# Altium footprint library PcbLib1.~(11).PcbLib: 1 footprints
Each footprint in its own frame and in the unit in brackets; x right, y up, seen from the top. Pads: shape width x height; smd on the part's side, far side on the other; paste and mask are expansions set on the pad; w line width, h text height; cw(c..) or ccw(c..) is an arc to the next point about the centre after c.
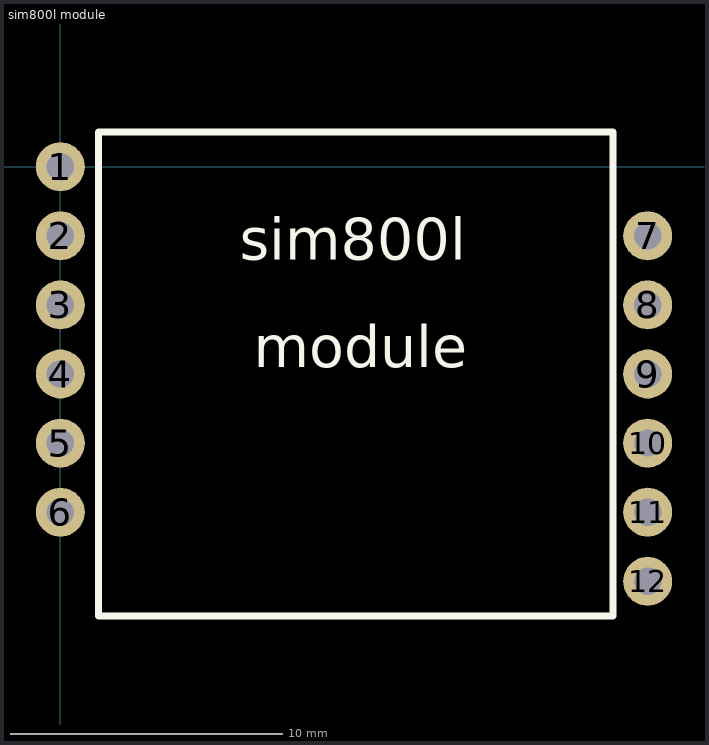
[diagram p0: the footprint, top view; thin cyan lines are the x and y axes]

## sim800l module [mm]
height 10
pads (12):
  round 1.8 hole 1: 1(0,0) 2(0,-2.54) 3(0,-5.08) 4(0,-7.62) 5(0,-10.16) 6(0,-12.7) 7(21.59,-2.54) 8(21.59,-5.08) 9(21.59,-7.62) 10(21.59,-10.16) 11(21.59,-12.7) 12(21.59,-15.24)
Top Overlay:
  lines w0.254: 1.397,-16.51 20.32,-16.51 20.32,1.27 19.939,1.27 1.397,1.27 1.397,-16.51
  text "module" at 7.112,-7.366 h1.52
  text "sim800l" at 6.604,-3.429 h1.52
